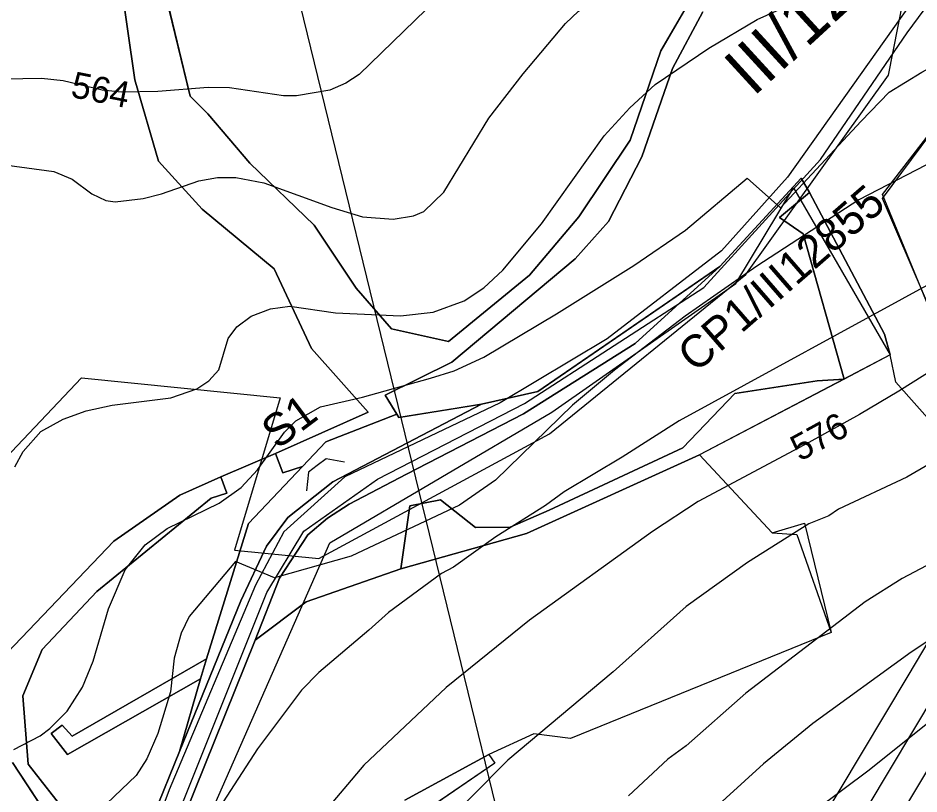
# Model space of a CAD drawing. Extents: x -709418 to -703832, y -1161719 to -1157826.
# Drawn here: x -707014.5 to -706737.7, y -1159133.3 to -1158895 of the extents above; entities that cross this region are included whole.
import ezdxf

# ---------------------------------------------------------------- set-up
doc = ezdxf.new("R2010")
doc.units = 0
for name, color, linetype in [('102_obvod PÚ', 7, 'Continuous'), ('103_hranice KÚ', 7, 'Continuous'), ('106_zastavitelné plochy', 7, 'Continuous'), ('110_silnice II. třídy a III. třídy', 7, 'Continuous'), ('111_silnice II. třídy a III. třídy_popis', 7, 'Continuous'), ('120_vrstevnice hlavní', 7, 'Continuous'), ('121_vrstevnice hlavní_popis', 7, 'Continuous'), ('122_vrstevnice základní', 7, 'Continuous'), ('206_TTP_KN', 7, 'Continuous'), ('210_ostatní plocha_KN', 7, 'Continuous'), ('303_příkop_stav', 7, 'Continuous'), ('306_hospodářský sjezd_stav', 7, 'Continuous'), ('309_OBJEKTY_stav_popis', 7, 'Continuous'), ('309_příkop_stav_popis', 7, 'Continuous'), ('514 odvodnění - LPIS', 7, 'Continuous'), ('705_el VN nadzemní_E.ON', 7, 'Continuous'), ('723_radioreléová trasa_UAP', 7, 'Continuous'), ('735_OP sítí TI', 7, 'Continuous')]:
    doc.layers.add(name, color=color, linetype=linetype)

msp = doc.modelspace()

# ---------------------------------------------------------------- linework, layer by layer
at = {"layer": '102_obvod PÚ'}
msp.add_lwpolyline([(-706804.13, -1158893.13), (-706813.42, -1158910.54), (-706822.8, -1158937.65), (-706833.12, -1158957.44), (-706843.37, -1158968.91), (-706881.2, -1159000.66), (-706901.7, -1159010.83), (-706897.53, -1159017.69), (-706872.15, -1159013.56), (-706854.79, -1159009.69), (-706798.85, -1158971.34), (-706773.86, -1158944.23), (-706771.36, -1158948.59), (-706748.32, -1158992.06), (-706746.57, -1158998.45), (-706805.12, -1159029.17), (-706782.76, -1159053.12), (-706775.23, -1159053.58), (-706764.62, -1159083.7), (-706844.79, -1159116.27), (-706856.08, -1159114.78), (-706869.86, -1159121.14), (-706867.98, -1159123.82), (-706903.51, -1159148.06)], dxfattribs=at)
at = {"layer": '103_hranice KÚ'}
msp.add_lwpolyline([(-706710.91, -1159044.97), (-706744.77, -1159006.87), (-706746.57, -1158998.45), (-706748.32, -1158992.06), (-706771.36, -1158948.59), (-706773.86, -1158944.23), (-706798.85, -1158971.34), (-706814.96, -1158982.38), (-706854.79, -1159009.69), (-706872.15, -1159013.56), (-706879.61, -1159014.77), (-706897.53, -1159017.69), (-706901.7, -1159010.83), (-706881.2, -1159000.66), (-706843.37, -1158968.91), (-706833.12, -1158957.44), (-706822.8, -1158937.65), (-706813.42, -1158910.54), (-706804.13, -1158893.13)], dxfattribs=at)
at = {"layer": '106_zastavitelné plochy'}
for points in [[(-706725.08, -1158918.48), (-706676.67, -1158919.85), (-706675.31, -1158989.35), (-706733.26, -1158987.31), (-706748.94, -1158949.15), (-706725.08, -1158918.48)], [(-706725.08, -1158918.48), (-706677.3, -1158919.11), (-706677.3, -1158992.02), (-706731.84, -1158989.98), (-706748.89, -1158950.45), (-706725.08, -1158918.48)], [(-706918.72, -1159056.21), (-706850.54, -1159016), (-706793.96, -1158976.48), (-706776.23, -1158947.18), (-706746.57, -1158998.45), (-706805.12, -1159029.17), (-706782.76, -1159053.12), (-706772.82, -1159050.08), (-706764.62, -1159083.7), (-706844.79, -1159116.27), (-706856.08, -1159114.78), (-706869.86, -1159121.14), (-706867.98, -1159123.82), (-706903.51, -1159148.06)], [(-707005.32, -1159252.75), (-706918.72, -1159056.21)]]:
    msp.add_lwpolyline(points, dxfattribs=at)
at = {"layer": '110_silnice II. třídy a III. třídy'}
msp.add_lwpolyline([(-706719.27, -1158868.19), (-706735.67, -1158884.09), (-706778.1, -1158943.84), (-706798.35, -1158966.48), (-706833.54, -1158993.47), (-706866.33, -1159013.22), (-706914.06, -1159035.87), (-706932.87, -1159052.74), (-706941.55, -1159069.12), (-706968.13, -1159131.99), (-706993.68, -1159200.89)], dxfattribs=at)
at = {"layer": '120_vrstevnice hlavní'}
for points in [[(-706790.47, -1158944.21), (-706780.23, -1158953.25), (-706755.48, -1158926.73), (-706746.84, -1158917.81), (-706736.79, -1158911.67), (-706724.69, -1158905.15), (-706709.26, -1158900.58), (-706698.98, -1158898.3), (-706683.55, -1158896.3), (-706668.4, -1158896.3), (-706654.69, -1158899.72), (-706636.4, -1158905.87), (-706627.26, -1158908.44), (-706608.97, -1158912.01), (-706590.69, -1158913.73), (-706577.33, -1158913.59), (-706567.05, -1158912.45), (-706552.54, -1158908.62)], [(-707015.85, -1159119.59), (-707007.71, -1159115.45), (-707004.71, -1159113.16), (-706999.42, -1159107.88), (-706994.71, -1159100.45), (-706991.42, -1159092.45), (-706986.71, -1159076.45), (-706981.56, -1159064.45), (-706975.42, -1159056.73), (-706968.7, -1159051.73), (-706952.7, -1159044.02), (-706945.99, -1159039.16), (-706940.99, -1159033.73), (-706932.7, -1159022.16), (-706929.13, -1159018.73), (-706921.56, -1159014.44), (-706908.7, -1159011.44), (-706887.81, -1159005.6), (-706880.56, -1159003.36), (-706871.35, -1158999.18), (-706849.04, -1158985.79), (-706825.33, -1158971), (-706809.44, -1158960.12), (-706790.47, -1158944.21)], [(-706565.97, -1159016.25), (-706586.43, -1159015.44), (-706591.54, -1159015.44), (-706630.12, -1159010.3), (-706638.69, -1159010.02), (-706647.26, -1159011.16), (-706655.83, -1159013.59), (-706660.12, -1159015.44), (-706668.4, -1159020.44), (-706684.26, -1159034.45), (-706691.98, -1159039.87), (-706700.12, -1159044.59), (-706742.84, -1159067.16), (-706754.27, -1159074.3), (-706790.84, -1159102.31), (-706809.27, -1159118.45), (-706814.84, -1159122.59), (-706826.94, -1159133.8)]]:
    msp.add_lwpolyline(points, dxfattribs=at)
at = {"layer": '122_vrstevnice základní'}
for points in [[(-706734.12, -1158812.29), (-706757.27, -1158813.58), (-706777.84, -1158817.86), (-706795.84, -1158823.72), (-706812.55, -1158831.15), (-706824.13, -1158837.44), (-706836.7, -1158845.86), (-706850.56, -1158856.58), (-706865.13, -1158869.01), (-706909.7, -1158912.3), (-706913.84, -1158915.01), (-706918.7, -1158917.15), (-706928.99, -1158918.87), (-706932.99, -1158918.87), (-706949.56, -1158916.44), (-706956.13, -1158916.3), (-706971.56, -1158917.58), (-706982.71, -1158917.73), (-706988.71, -1158917.15), (-707000.71, -1158914.3), (-707007.28, -1158913.58), (-707024.71, -1158913.87)], [(-707017.85, -1158940.15), (-707003.56, -1158942.16), (-706997.85, -1158944.44), (-706991.85, -1158949.01), (-706987.56, -1158951.01), (-706984.71, -1158951.44), (-706976.13, -1158950.44), (-706970.42, -1158949.01), (-706958.99, -1158945.01), (-706953.28, -1158944.01), (-706947.56, -1158944.01), (-706938.99, -1158945.58), (-706918.13, -1158953.16), (-706908.7, -1158956.01), (-706899.27, -1158956.73), (-706892.99, -1158955.73), (-706889.84, -1158954.44), (-706883.7, -1158948.44), (-706869.84, -1158925.73), (-706859.3, -1158912.11), (-706846.27, -1158896.72), (-706842.27, -1158892.87), (-706813.12, -1158870.29), (-706791.84, -1158856.58)], [(-707015.56, -1159032.87), (-707012.99, -1159028.16), (-707007.56, -1159022.02), (-707000.71, -1159018.16), (-706993.56, -1159015.59), (-706985.56, -1159013.87), (-706967.56, -1159011.59), (-706959.56, -1159008.87), (-706955.85, -1159006.44), (-706952.85, -1159003.02), (-706949.99, -1158993.44), (-706947.27, -1158989.87), (-706942.85, -1158986.59), (-706936.99, -1158984.3), (-706930.99, -1158983.44), (-706916.99, -1158985.58), (-706896.99, -1158986.44), (-706886.99, -1158985.3), (-706877.41, -1158981.87), (-706871.41, -1158977.87), (-706865.56, -1158972.44), (-706853.7, -1158958.16), (-706834.41, -1158931.15), (-706826.55, -1158922.58), (-706818.7, -1158915.44), (-706802.27, -1158904.3), (-706787.41, -1158895.44), (-706768.69, -1158887.01)], [(-706735.55, -1158940.16), (-706756.12, -1158950.87), (-706787.55, -1158971.16), (-706809.55, -1158986.59), (-706831.27, -1159003.16), (-706844.13, -1159013.87), (-706867.84, -1159036.87), (-706878.84, -1159044.59), (-706912.13, -1159060.3), (-706935.69, -1159066.92), (-706947.69, -1159061.9), (-706961.99, -1159078.73), (-706964.42, -1159083.88), (-706966.56, -1159091.59), (-706967.7, -1159101.88), (-706971.56, -1159114.74), (-706974.99, -1159122.45), (-706978.28, -1159127.59), (-706994.13, -1159142.74)], [(-706560.95, -1158976.03), (-706589.26, -1158976.73), (-706606.4, -1158974.44), (-706625.26, -1158969.58), (-706638.97, -1158967.87), (-706647.55, -1158967.87), (-706662.97, -1158969.73), (-706671.55, -1158971.58), (-706681.83, -1158975.01), (-706705.83, -1158986.3), (-706715.55, -1158991.73), (-706743.84, -1159009.59), (-706755.98, -1159016.73), (-706771.55, -1159025.3), (-706805.55, -1159043.45), (-706819.55, -1159052.73), (-706857.41, -1159079.88), (-706882.98, -1159100.59), (-706908.27, -1159124.45), (-706928.99, -1159148.88)], [(-706732.98, -1158975.87), (-706811.41, -1159018.73), (-706828.84, -1159029.87), (-706846.7, -1159040.45), (-706852.41, -1159044.73), (-706867.7, -1159054.3), (-706880.7, -1159063.59), (-706884.41, -1159065.59), (-706900.7, -1159077.59), (-706906.7, -1159083.02), (-706922.13, -1159096.02), (-706927.42, -1159101.45), (-706940.99, -1159119.45), (-706962.28, -1159152.31)], [(-706563.77, -1158998.62), (-706576.67, -1158998.58), (-706590.16, -1158997.59), (-706601.26, -1158995.87), (-706619.54, -1158993.87), (-706641.55, -1158993.01), (-706657.55, -1158994.16), (-706665.55, -1158995.87), (-706675.83, -1158999.3), (-706694.12, -1159008.44), (-706741.41, -1159036.02), (-706762.41, -1159045.87), (-706765.41, -1159047.87), (-706771.55, -1159050.3), (-706790.41, -1159062.16), (-706809.27, -1159075.73), (-706831.7, -1159095.73), (-706863.98, -1159122.88), (-706885.84, -1159144.88)], [(-706567.77, -1159030.76), (-706609.83, -1159031.02), (-706632.12, -1159031.59), (-706638.97, -1159032.3), (-706654.4, -1159036.59), (-706672.4, -1159045.87), (-706698.83, -1159063.59), (-706717.41, -1159074.73), (-706740.12, -1159089.73), (-706770.27, -1159111.59), (-706785.41, -1159124.02), (-706808.41, -1159144.88), (-706817.27, -1159154.02), (-706820.27, -1159157.88), (-706874.34, -1159216.6)], [(-706896.34, -1159305.76), (-706891.06, -1159299.33), (-706868.97, -1159246.1), (-706862.43, -1159234.32), (-706837.41, -1159204.45), (-706811.55, -1159175.45), (-706794.98, -1159159.17), (-706778.12, -1159144.59), (-706752.98, -1159125.88), (-706702.69, -1159085.59), (-706687.55, -1159074.88), (-706663.69, -1159061.59), (-706650.83, -1159056.16), (-706631.55, -1159049.87), (-706622.97, -1159047.87), (-706605.83, -1159045.3), (-706569.16, -1159041.88)]]:
    msp.add_lwpolyline(points, dxfattribs=at)
at = {"layer": '206_TTP_KN'}
for p, q in [((-706786.71, -1158853.08), (-706817.04, -1158905.1)), ((-706961.67, -1158919.05), (-706971.09, -1158879.8)), ((-706817.04, -1158905.1), (-706826.46, -1158932.5)), ((-706956.18, -1158924.47), (-706961.67, -1158919.05)), ((-706943.33, -1158939.53), (-706956.18, -1158924.47)), ((-706826.46, -1158932.5), (-706842.25, -1158956.05)), ((-706923.49, -1158958.65), (-706943.33, -1158939.53)), ((-706798.85, -1158971.34), (-706773.86, -1158944.23)), ((-706773.86, -1158944.23), (-706771.36, -1158948.59)), ((-706771.36, -1158948.59), (-706780.56, -1158956.29)), ((-706842.25, -1158956.05), (-706857.41, -1158974)), ((-706780.56, -1158956.29), (-706773.32, -1158961.29)), ((-706910.58, -1158977.99), (-706923.49, -1158958.65)), ((-706773.32, -1158961.29), (-706760.69, -1159005.86)), ((-706824.92, -1158994.96), (-706798.85, -1158971.34)), ((-706857.41, -1158974), (-706882.25, -1158994.33)), ((-706899.73, -1158990.48), (-706910.58, -1158977.99)), ((-706882.25, -1158994.33), (-706899.73, -1158990.48)), ((-706859.17, -1159016.52), (-706824.92, -1158994.96)), ((-706769, -1159006.39), (-706794.26, -1159010.33)), ((-706760.69, -1159005.86), (-706769, -1159006.39)), ((-706794.26, -1159010.33), (-706810.24, -1159027.03)), ((-706895.2, -1159035.06), (-706859.17, -1159016.52)), ((-706810.24, -1159027.03), (-706851.28, -1159046.15)), ((-706952.2, -1159035.94), (-706935.45, -1159028.71)), ((-706935.45, -1159028.71), (-706933.13, -1159034.67)), ((-706858.31, -1159053.25), (-706805.12, -1159029.17)), ((-706805.12, -1159029.17), (-706782.76, -1159053.12)), ((-706927.1, -1159032.74), (-706943.74, -1159050.19)), ((-706933.13, -1159034.67), (-706927.1, -1159032.74)), ((-706950.34, -1159040.86), (-706952.2, -1159035.94)), ((-706912.75, -1159044.33), (-706895.2, -1159035.06)), ((-706955.23, -1159042.4), (-706950.34, -1159040.86)), ((-706990.27, -1159071.09), (-706955.23, -1159042.4)), ((-706919.46, -1159048.61), (-706912.75, -1159044.33)), ((-706884.67, -1159042.94), (-706894.09, -1159044.8)), ((-706873.97, -1159051.43), (-706884.67, -1159042.94)), ((-706894.09, -1159044.8), (-706896.89, -1159064.19)), ((-706851.28, -1159046.15), (-706863.26, -1159051.36)), ((-706925.45, -1159053.75), (-706919.46, -1159048.61)), ((-706943.74, -1159050.19), (-706956.6, -1159091.82)), ((-706863.26, -1159051.36), (-706873.97, -1159051.43)), ((-706934.16, -1159067.02), (-706925.45, -1159053.75)), ((-706896.89, -1159064.19), (-706858.31, -1159053.25)), ((-706782.76, -1159053.12), (-706775.23, -1159053.58)), ((-706775.23, -1159053.58), (-706764.62, -1159083.7)), ((-706926.01, -1159074.32), (-706896.89, -1159064.19)), ((-706896.89, -1159064.19), (-706926.01, -1159074.32)), ((-706941.64, -1159086.02), (-706934.16, -1159067.02)), ((-707007.07, -1159088.89), (-706990.27, -1159071.09)), ((-706941.64, -1159086.02), (-706926.01, -1159074.32)), ((-706926.01, -1159074.32), (-706941.64, -1159086.02)), ((-706764.62, -1159083.7), (-706844.79, -1159116.27)), ((-706974.94, -1159168.61), (-706941.64, -1159086.02)), ((-707013.1, -1159103.13), (-707007.07, -1159088.89)), ((-706956.6, -1159091.82), (-706997.87, -1159115.56)), ((-706997.87, -1159115.56), (-706956.6, -1159091.82)), ((-706956.6, -1159091.82), (-706958.43, -1159097.89)), ((-706999.36, -1159121.17), (-706958.43, -1159097.89)), ((-706958.43, -1159097.89), (-706999.36, -1159121.17)), ((-706958.43, -1159097.89), (-706964.92, -1159120.2)), ((-707011.39, -1159124.11), (-707013.1, -1159103.13)), ((-707001, -1159112.18), (-707004.37, -1159114.7)), ((-707004.37, -1159114.7), (-707001, -1159112.18)), ((-706997.87, -1159115.56), (-707001, -1159112.18)), ((-707001, -1159112.18), (-706997.87, -1159115.56)), ((-707004.37, -1159114.7), (-706999.36, -1159121.17)), ((-706999.36, -1159121.17), (-707004.37, -1159114.7)), ((-706856.08, -1159114.78), (-706869.86, -1159121.14)), ((-706844.79, -1159116.27), (-706856.08, -1159114.78)), ((-706964.92, -1159120.2), (-706981.85, -1159161.86)), ((-706869.86, -1159121.14), (-706895.72, -1159135.14)), ((-706981.85, -1159161.86), (-707011.39, -1159124.11))]:
    msp.add_line(p, q, dxfattribs=at)
for points in [[(-706971.3, -1158861.59), (-706971.09, -1158879.8), (-706961.67, -1158919.05), (-706956.18, -1158924.47), (-706943.33, -1158939.53), (-706923.49, -1158958.65), (-706910.58, -1158977.99), (-706899.73, -1158990.48), (-706882.25, -1158994.33), (-706857.41, -1158974), (-706842.25, -1158956.05), (-706826.46, -1158932.5), (-706817.04, -1158905.1), (-706786.71, -1158853.08), (-706761.38, -1158825.82), (-706749.54, -1158810.97), (-706776.15, -1158794.56), (-706800.81, -1158780.54), (-706819.5, -1158787.85), (-706835.42, -1158791.85), (-706892.15, -1158802.41), (-706910.63, -1158811.55), (-706954.36, -1158836.04), (-706971.3, -1158861.59)], [(-707020.53, -1158821.14), (-707003.05, -1158821.86), (-706989.79, -1158831.33), (-706981.05, -1158841.86), (-706980.98, -1158849.88), (-706983.9, -1158867.3), (-706983.02, -1158883.23), (-706978.59, -1158914.02), (-706971.35, -1158938.92), (-706957.97, -1158953.73), (-706935.85, -1158972), (-706924.4, -1158996.47), (-706906.91, -1159016.08), (-706935.45, -1159028.71), (-706952.2, -1159035.94), (-706964.79, -1159041.54), (-706985.11, -1159055.65), (-707020.15, -1159092.19)], [(-706804.13, -1158893.13), (-706813.42, -1158910.54), (-706822.8, -1158937.65), (-706833.12, -1158957.44), (-706843.37, -1158968.91), (-706881.2, -1159000.66), (-706901.7, -1159010.83), (-706898.15, -1159016.67), (-706919.93, -1159025.11), (-706927.1, -1159032.74), (-706933.13, -1159034.67), (-706935.45, -1159028.71), (-706906.91, -1159016.08), (-706924.4, -1158996.47), (-706935.85, -1158972), (-706957.97, -1158953.73), (-706971.35, -1158938.92), (-706978.59, -1158914.02), (-706983.02, -1158883.23)], [(-707016.26, -1159123.62), (-706985.49, -1159170.3)]]:
    msp.add_lwpolyline(points, dxfattribs=at)
at = {"layer": '210_ostatní plocha_KN'}
for p, q in [((-706780.56, -1158956.29), (-706771.36, -1158948.59)), ((-706771.36, -1158948.59), (-706748.32, -1158992.06)), ((-706773.32, -1158961.29), (-706780.56, -1158956.29)), ((-706760.69, -1159005.86), (-706773.32, -1158961.29)), ((-706854.79, -1159009.69), (-706798.85, -1158971.34)), ((-706798.85, -1158971.34), (-706824.92, -1158994.96)), ((-706748.32, -1158992.06), (-706746.57, -1158998.45)), ((-706824.92, -1158994.96), (-706859.17, -1159016.52)), ((-706746.57, -1158998.45), (-706760.69, -1159005.86)), ((-706760.69, -1159005.86), (-706805.12, -1159029.17)), ((-706794.26, -1159010.33), (-706769, -1159006.39)), ((-706769, -1159006.39), (-706760.69, -1159005.86)), ((-706872.15, -1159013.56), (-706854.79, -1159009.69)), ((-706810.24, -1159027.03), (-706794.26, -1159010.33)), ((-706917.82, -1159037.46), (-706872.15, -1159013.56)), ((-706872.15, -1159013.56), (-706917.82, -1159037.46)), ((-706897.53, -1159017.69), (-706872.15, -1159013.56)), ((-706859.17, -1159016.52), (-706895.2, -1159035.06)), ((-706919.93, -1159025.11), (-706898.15, -1159016.67)), ((-706898.15, -1159016.67), (-706897.53, -1159017.69)), ((-706927.1, -1159032.74), (-706919.93, -1159025.11)), ((-706851.28, -1159046.15), (-706810.24, -1159027.03)), ((-706805.12, -1159029.17), (-706858.31, -1159053.25)), ((-706943.74, -1159050.19), (-706927.1, -1159032.74)), ((-706964.79, -1159041.54), (-706952.2, -1159035.94)), ((-706952.2, -1159035.94), (-706950.34, -1159040.86)), ((-706895.2, -1159035.06), (-706912.75, -1159044.33)), ((-706931.59, -1159048.38), (-706917.82, -1159037.46)), ((-706917.82, -1159037.46), (-706931.59, -1159048.38)), ((-706985.11, -1159055.65), (-706964.79, -1159041.54)), ((-706950.34, -1159040.86), (-706955.23, -1159042.4)), ((-706955.23, -1159042.4), (-706990.27, -1159071.09)), ((-706912.75, -1159044.33), (-706919.46, -1159048.61)), ((-706894.09, -1159044.8), (-706884.67, -1159042.94)), ((-706884.67, -1159042.94), (-706873.97, -1159051.43)), ((-706896.89, -1159064.19), (-706894.09, -1159044.8)), ((-706863.26, -1159051.36), (-706851.28, -1159046.15)), ((-706938.16, -1159057.23), (-706931.59, -1159048.38)), ((-706931.59, -1159048.38), (-706938.16, -1159057.23)), ((-706919.46, -1159048.61), (-706925.45, -1159053.75)), ((-706956.6, -1159091.82), (-706943.74, -1159050.19)), ((-706873.97, -1159051.43), (-706863.26, -1159051.36)), ((-706925.45, -1159053.75), (-706934.16, -1159067.02)), ((-706858.31, -1159053.25), (-706896.89, -1159064.19)), ((-707020.15, -1159092.19), (-706985.11, -1159055.65)), ((-706946.06, -1159074.01), (-706938.16, -1159057.23)), ((-706938.16, -1159057.23), (-706946.06, -1159074.01)), ((-706934.16, -1159067.02), (-706941.64, -1159086.02)), ((-706990.27, -1159071.09), (-707007.07, -1159088.89)), ((-706964.92, -1159120.2), (-706946.06, -1159074.01)), ((-706946.06, -1159074.01), (-706964.92, -1159120.2)), ((-706941.64, -1159086.02), (-706974.94, -1159168.61)), ((-707007.07, -1159088.89), (-707013.1, -1159103.13)), ((-706958.43, -1159097.89), (-706956.6, -1159091.82)), ((-706964.92, -1159120.2), (-706958.43, -1159097.89)), ((-707013.1, -1159103.13), (-707011.39, -1159124.11)), ((-706981.85, -1159161.86), (-706964.92, -1159120.2)), ((-706895.72, -1159135.14), (-706869.86, -1159121.14)), ((-706869.86, -1159121.14), (-706867.98, -1159123.82)), ((-706985.49, -1159170.3), (-707016.26, -1159123.62)), ((-707011.39, -1159124.11), (-706981.85, -1159161.86)), ((-706867.98, -1159123.82), (-706903.51, -1159148.06))]:
    msp.add_line(p, q, dxfattribs=at)
at = {"layer": '303_příkop_stav'}
msp.add_lwpolyline([(-706972.54, -1159157.44), (-706938.1, -1159071.4), (-706926.7, -1159052.56), (-706904.04, -1159036.6), (-706858.9, -1159013.34), (-706803.75, -1158977.76), (-706767.91, -1158938.46), (-706741.34, -1158899.51), (-706730.87, -1158885.33), (-706718.54, -1158876.26), (-706713.89, -1158874.63)], dxfattribs=at)
at = {"layer": '306_hospodářský sjezd_stav'}
msp.add_lwpolyline([(-706914.18, -1159031.39), (-706919.89, -1159030.35), (-706922.6, -1159032.39), (-706925.31, -1159034.43), (-706925.89, -1159040.21)], dxfattribs=at)
at = {"layer": '514 odvodnění - LPIS'}
msp.add_lwpolyline([(-707091.66, -1159185.61), (-707067.05, -1159100.92), (-707036.31, -1159048.98), (-706995.04, -1159005.45), (-706934.01, -1159011.63), (-706947.99, -1159058.39), (-706922.15, -1159060.93), (-706851.26, -1159022.69), (-706790.89, -1158973.74), (-706747.02, -1158912.58), (-706716.93, -1158759.9), (-706697.06, -1158726.14), (-706670.64, -1158725.93), (-706602.78, -1158847.92), (-706583.04, -1158891.24), (-706552.73, -1158910.18), (-706494.68, -1158910.47), (-706457.47, -1158890.53), (-706273.62, -1158913.9)], dxfattribs=at)
at = {"layer": '705_el VN nadzemní_E.ON'}
msp.add_lwpolyline([(-706880.73, -1160218.11), (-706883.24, -1160121.67), (-706885.97, -1160030.15), (-706888.81, -1159867.66), (-706890.66, -1159770.11), (-706893.19, -1159670.63), (-706895.78, -1159542.24), (-706897.96, -1159421.41), (-706883.28, -1159376.25), (-706867.82, -1159329.09), (-706796.05, -1159208.33), (-706732.4, -1159102.13), (-706682.71, -1159018.58)], dxfattribs=at)
at = {"layer": '723_radioreléová trasa_UAP'}
msp.add_lwpolyline([(-707182.2, -1157850.62), (-706271.36, -1161577.76)], dxfattribs=at)
at = {"layer": '735_OP sítí TI'}
for points in [[(-706890.9, -1160211.71), (-706893.24, -1160121.95), (-706895.97, -1160030.39), (-706898.81, -1159867.84), (-706900.66, -1159770.33), (-706903.19, -1159670.86), (-706905.78, -1159542.43), (-706907.99, -1159419.91), (-706892.79, -1159373.15), (-706876.98, -1159324.93), (-706804.64, -1159203.21), (-706740.99, -1159097), (-706691.31, -1159013.46)], [(-706870.8, -1160215.44), (-706873.24, -1160121.39), (-706875.97, -1160029.91), (-706878.81, -1159867.48), (-706880.66, -1159769.89), (-706883.19, -1159670.4), (-706885.78, -1159542.05), (-706887.93, -1159422.91), (-706873.77, -1159379.35), (-706858.66, -1159333.25), (-706787.46, -1159213.45), (-706723.81, -1159107.26), (-706674.12, -1159023.69)]]:
    msp.add_lwpolyline(points, dxfattribs=at)

# ---------------------------------------------------------------- texts
at = {"layer": '111_silnice II. třídy a III. třídy_popis'}
msp.add_text('III/12855', height=15, rotation=42.5281, dxfattribs=at).set_placement((-706788.64, -1158919.44))
at = {"layer": '121_vrstevnice hlavní_popis'}
for s, rotation, p in [('564', 348.7652, (-706998.65, -1158919.2)), ('576', 28.6219, (-706774.29, -1159031.3))]:
    msp.add_text(s, height=8, rotation=rotation, dxfattribs=at).set_placement(p)
at = {"layer": '309_OBJEKTY_stav_popis'}
msp.add_text('S1', height=10, rotation=36.9934, dxfattribs=at).set_placement((-706934.81, -1159027.71))
at = {"layer": '309_příkop_stav_popis'}
msp.add_text('CP1/III12855', height=10, rotation=41.0527, dxfattribs=at).set_placement((-706806.29, -1159004.23))

doc.saveas('drawing.dxf')
